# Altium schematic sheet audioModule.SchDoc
size A4
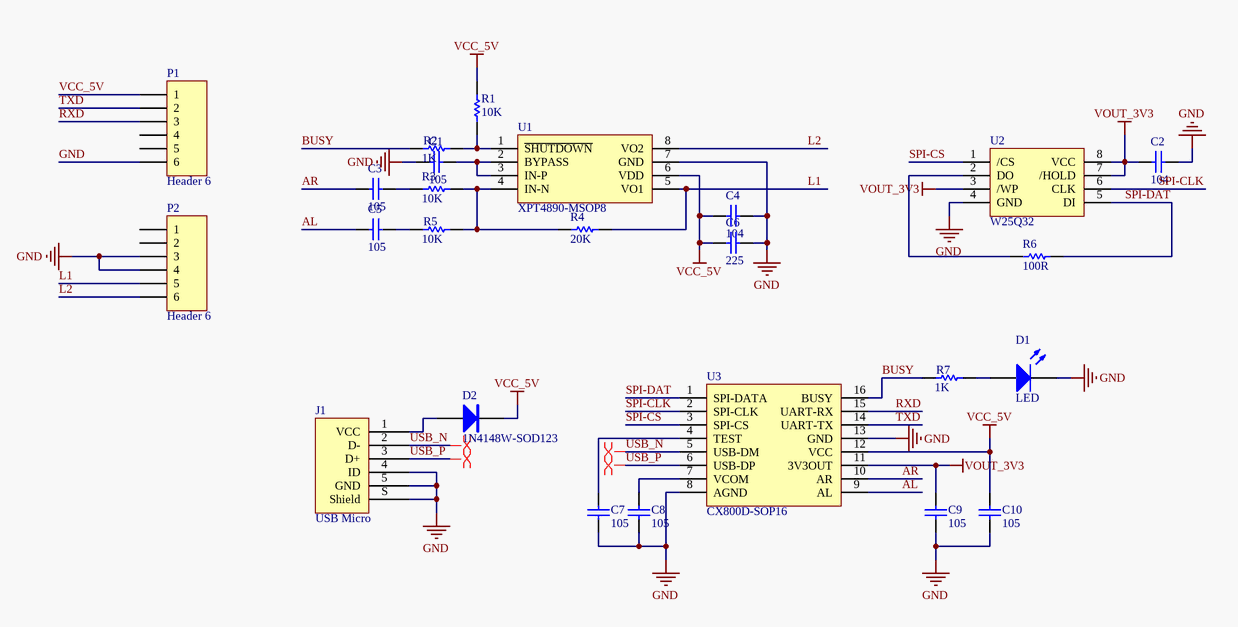
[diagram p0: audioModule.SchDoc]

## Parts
C1  value 105  [B0603C]  (hidden comment: Cap Semi)
C2  value 104  [B0603C]  (hidden comment: Cap Semi)
C3  value 105  [B0603C]  (hidden comment: Cap Semi)
C4  value 104  [B0603C]  (hidden comment: Cap Semi)
C5  value 105  [B0603C]  (hidden comment: Cap Semi)
C6  value 225  [B0603C]  (hidden comment: Cap Semi)
C7  value 105  [B0603C]  (hidden comment: Cap Semi)
C8  value 105  [B0603C]  (hidden comment: Cap Semi)
C9  value 105  [B0603C]  (hidden comment: Cap Semi)
C10  value 105  [B0603C]  (hidden comment: Cap Semi)
D1  LED  [LED_0603]
D2  1N4148W-SOD123  [SOD123]
J1  USB Micro  [USB2.0-Micro-TypeB-03]
P1  Header 6  [HDR1X6]
P2  Header 6  [HDR1X6]
R1  value 10K  [B0603R]  (hidden comment: Res Semi)
R2  value 1K  [B0603R]  (hidden comment: Res Semi)
R3  value 10K  [B0603R]  (hidden comment: Res Semi)
R4  value 20K  [B0603R]  (hidden comment: Res Semi)
R5  value 10K  [B0603R]  (hidden comment: Res Semi)
R6  value 100R  [B0603R]  (hidden comment: Res Semi)
R7  value 1K  [B0603R]  (hidden comment: Res Semi)
U1  XPT4890-MSOP8  [XPT4890MS-MSOP8]
U2  W25Q32  [SOIC127P790X216-8N]
U3  CX800D-SOP16  [SOP16N]

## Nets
GND: C1.2 C2.1 C4.2 C6.2 C7.2 C8.2 C9.2 C10.2 D1.K J1.4(ID) J1.5(GND) J1.S(Shield) P1.6 P2.3 P2.4 U1.7(GND) U2.4(GND) U3.8(AGND) U3.13(GND)
VCC_5V: C4.1 C6.1 C10.1 D2.K P1.1 R1.2 U1.6(VDD) U3.12(VCC)
VOUT_3V3: C2.2 C9.1 U2.3(/WP) U2.7(/HOLD) U2.8(VCC) U3.11(3V3OUT)
AL: C5.1 U3.9(AL)
AR: C3.1 U3.10(AR)
BUSY: R2.1 R7.1 U3.16(BUSY)
L1: P2.5 R4.2 U1.5(VO1)
L2: P2.6 U1.8(VO2)
RXD: P1.3 U3.15(UART-RX)
SPI-CLK: U2.6(CLK) U3.2(SPI-CLK)
SPI-CS: U2.1(/CS) U3.3(SPI-CS)
SPI-DAT: R6.2 U2.5(DI) U3.1(SPI-DATA)
TXD: P1.2 U3.14(UART-TX)
USB_N: J1.2(D-) U3.5(USB-DM)
USB_P: J1.3(D+) U3.6(USB-DP)
NetC1_1: C1.1 U1.2(BYPASS) U1.3(IN-P)
NetC3_2: C3.2 R3.1
NetC5_2: C5.2 R5.1
NetC7_1: C7.1 U3.4(TEST)
NetC8_1: C8.1 U3.7(VCOM)
NetD1_A: D1.A R7.2
NetD2_A: D2.A J1.1(VCC)
NetR1_1: R1.1 R2.2 U1.1(~{SHUTDOWN})
NetR3_2: R3.2 R4.1 R5.2 U1.4(IN-N)
NetR6_1: R6.1 U2.2(DO)

Not connected (* = marked no-connect by the designer): P1 4 5; P2 1 2

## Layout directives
differential pair: USB_N, USB_P

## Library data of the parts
C1-C10 = Cap Semi: Capacitor (Semiconductor SIM Model)
D2 = 1N5822: Diode
J1 = USB 2.0 Type B Micro
P1 P2 = Header 6: Header, 6-Pin
R1-R7 = Res Semi: Semiconductor Resistor
U1 = XPT4890: AudioPowerAmplifierIC
U2 = W25Q16
U3 = CX800D: AudioIC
